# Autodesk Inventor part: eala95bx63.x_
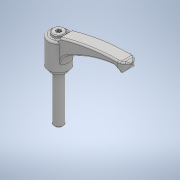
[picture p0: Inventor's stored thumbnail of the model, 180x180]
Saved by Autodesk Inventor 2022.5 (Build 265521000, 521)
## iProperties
Created: 2018-05
Part Number: eala95bx63.x_
Material: 一般
Document SubType Name: Modeling
Designer: imaocorp
Density: 1 g/cm^3
Appearance: 既定
Sending System: SOLIDWORKS 2016-2016286
MC: AMD64
MC_MODEL: AMD64 Family 21 Model 2 Stepping 0, AuthenticAMD
OS: Windows_NT
FRU: Parasolid Version 28.0, build 224,  7-29-2016
FORMAT: text
GUISE: transmit
KEY: eala95bx63
FILE: eala95bx63.x_t
DATE: Fri May 18 11:34:06 2018
Author: imaocorp
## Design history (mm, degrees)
feature "Base1"
node "ソリッド1"
